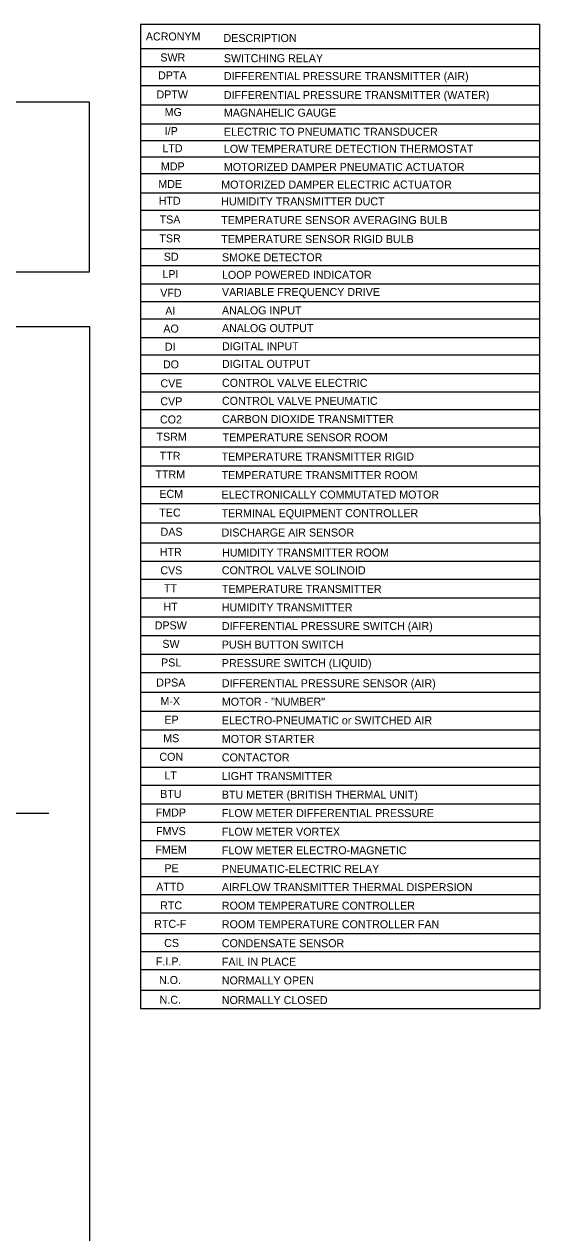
# Model space of a CAD drawing. Extents: x 10015 to 10283, y 10002 to 10184.
# Drawn here: x 10212.9 to 10255.9, y 10083.5 to 10184.2 of the extents above; entities that cross this region are included whole.
import ezdxf

# ---------------------------------------------------------------- set-up
doc = ezdxf.new("R2010")
doc.units = 0
for name, color, linetype in [('G-ANNO-TEXT', 7, 'Continuous'), ('G-DETL-LINE', 7, 'Continuous'), ('G-SCHD-LINE', 7, 'Continuous'), ('G-SCHD-TEXT', 7, 'Continuous'), ('M-ANNO-NPLT', 7, 'Continuous')]:
    doc.layers.add(name, color=color, linetype=linetype)

msp = doc.modelspace()

# ---------------------------------------------------------------- linework, layer by layer
at = {"layer": 'G-ANNO-TEXT'}
msp.add_line((10206.45, 10118.48), (10214.98, 10118.48), dxfattribs=at)
at = {"layer": 'G-DETL-LINE'}
msp.add_lwpolyline([(10127.5, 10177.76), (10218.36, 10177.76), (10218.36, 10163.56), (10127.5, 10163.56)], close=True, dxfattribs=at)
msp.add_lwpolyline([(10164.66, 10159.01), (10164.66, 10134.54), (10132.98, 10134.54), (10132.98, 10061.02), (10218.41, 10061.02), (10218.41, 10159.01), (10164.66, 10159.01)], dxfattribs=at)
at = {"layer": 'G-SCHD-LINE'}
for p, q in [((10222.64, 10184.22), (10222.65, 10102.19)), ((10222.64, 10184.22), (10255.92, 10184.22)), ((10255.92, 10184.22), (10255.94, 10102.19)), ((10222.64, 10182.19), (10255.92, 10182.19)), ((10222.64, 10180.69), (10255.92, 10180.69)), ((10222.64, 10179.1), (10255.92, 10179.1)), ((10222.64, 10177.5), (10255.92, 10177.5)), ((10222.64, 10175.91), (10255.92, 10175.91)), ((10222.64, 10174.53), (10255.92, 10174.53)), ((10222.64, 10173.16), (10255.92, 10173.16)), ((10222.64, 10171.78), (10255.92, 10171.78)), ((10222.64, 10170.16), (10255.92, 10170.16)), ((10222.64, 10168.72), (10255.92, 10168.72)), ((10222.64, 10167.07), (10255.92, 10167.07)), ((10222.64, 10165.53), (10255.92, 10165.53)), ((10222.64, 10164.1), (10255.92, 10164.1)), ((10222.64, 10162.59), (10255.92, 10162.59)), ((10222.64, 10161.12), (10255.92, 10161.12)), ((10222.64, 10159.66), (10255.92, 10159.66)), ((10222.64, 10158.11), (10255.92, 10158.11)), ((10222.64, 10156.67), (10255.92, 10156.67)), ((10222.64, 10155.12), (10255.92, 10155.12)), ((10222.64, 10153.58), (10255.92, 10153.58)), ((10222.64, 10152.1), (10255.92, 10152.1)), ((10222.64, 10150.59), (10255.92, 10150.59)), ((10222.64, 10148.99), (10255.92, 10148.99)), ((10222.64, 10147.42), (10255.92, 10147.42)), ((10222.64, 10145.71), (10255.92, 10145.71)), ((10222.64, 10144.27), (10255.92, 10144.27)), ((10222.64, 10142.68), (10255.92, 10142.68)), ((10222.64, 10141), (10255.92, 10141)), ((10222.64, 10139.47), (10255.92, 10139.47)), ((10222.64, 10137.98), (10255.92, 10137.98)), ((10222.64, 10136.41), (10255.92, 10136.41)), ((10222.64, 10134.84), (10255.92, 10134.84)), ((10222.64, 10133.27), (10255.92, 10133.27)), ((10222.64, 10131.72), (10255.92, 10131.72)), ((10222.64, 10130.21), (10255.92, 10130.21)), ((10222.64, 10128.55), (10255.92, 10128.55)), ((10222.64, 10126.99), (10255.92, 10126.99)), ((10222.64, 10125.42), (10255.92, 10125.42)), ((10222.64, 10123.89), (10255.92, 10123.89)), ((10222.64, 10122.32), (10255.92, 10122.32)), ((10222.64, 10120.8), (10255.92, 10120.8)), ((10222.64, 10119.25), (10255.92, 10119.25)), ((10222.64, 10117.72), (10255.92, 10117.72)), ((10222.64, 10116.21), (10255.92, 10116.21)), ((10222.64, 10114.7), (10255.92, 10114.7)), ((10222.64, 10113.2), (10255.92, 10113.2)), ((10222.64, 10111.69), (10255.92, 10111.69)), ((10222.64, 10110.18), (10255.92, 10110.18)), ((10222.64, 10108.46), (10255.92, 10108.46)), ((10222.64, 10106.95), (10255.92, 10106.95)), ((10222.64, 10105.44), (10255.92, 10105.44)), ((10222.64, 10103.72), (10255.92, 10103.72)), ((10222.65, 10102.19), (10255.94, 10102.19))]:
    msp.add_line(p, q, dxfattribs=at)

# ---------------------------------------------------------------- texts
at = {"layer": 'G-SCHD-TEXT'}
for s, height, p in [('ACRONYM', 0.667, (10223.08, 10182.86)), ('DESCRIPTION', 0.6667, (10229.56, 10182.73)), ('SWR', 0.667, (10224.29, 10181.11)), ('SWITCHING RELAY', 0.6667, (10229.59, 10181.05)), ('DPTA', 0.667, (10224.1, 10179.62)), ('DIFFERENTIAL PRESSURE TRANSMITTER (AIR)', 0.6667, (10229.59, 10179.56)), ('DPTW', 0.667, (10223.97, 10178.03)), ('DIFFERENTIAL PRESSURE TRANSMITTER (WATER)', 0.6667, (10229.59, 10177.98)), ('MG', 0.667, (10224.65, 10176.56)), ('MAGNAHELIC GAUGE', 0.6667, (10229.59, 10176.51)), ('I/P', 0.667, (10224.66, 10174.98)), ('ELECTRIC TO PNEUMATIC TRANSDUCER', 0.6667, (10229.59, 10174.92)), ('LTD', 0.667, (10224.46, 10173.55)), ('LOW TEMPERATURE DETECTION THERMOSTAT', 0.6667, (10229.59, 10173.5)), ('MDP', 0.667, (10224.34, 10172.04)), ('MOTORIZED DAMPER PNEUMATIC ACTUATOR', 0.6667, (10229.59, 10171.99)), ('MDE', 0.667, (10224.12, 10170.57)), ('MOTORIZED DAMPER ELECTRIC ACTUATOR', 0.6667, (10229.37, 10170.52)), ('HTD', 0.667, (10224.15, 10169.17)), ('HUMIDITY TRANSMITTER DUCT', 0.6667, (10229.37, 10169.12)), ('TSA', 0.667, (10224.23, 10167.61)), ('TEMPERATURE SENSOR AVERAGING BULB', 0.6667, (10229.37, 10167.56)), ('TSR', 0.667, (10224.21, 10166.04)), ('TEMPERATURE SENSOR RIGID BULB', 0.6667, (10229.37, 10165.98)), ('SD', 0.667, (10224.58, 10164.51)), ('SMOKE DETECTOR', 0.6667, (10229.43, 10164.46)), ('LPI', 0.667, (10224.46, 10163.06)), ('LOOP POWERED INDICATOR', 0.6667, (10229.43, 10163)), ('VFD', 0.667, (10224.28, 10161.5)), ('VARIABLE FREQUENCY DRIVE', 0.6667, (10229.43, 10161.57)), ('AI', 0.667, (10224.7, 10160)), ('ANALOG INPUT', 0.6667, (10229.43, 10160.04)), ('ANALOG OUTPUT', 0.6667, (10229.43, 10158.56)), ('AO', 0.667, (10224.54, 10158.52)), ('DI', 0.667, (10224.67, 10157.01)), ('DIGITAL INPUT', 0.6667, (10229.43, 10157.05)), ('DO', 0.667, (10224.51, 10155.54)), ('DIGITAL OUTPUT', 0.6667, (10229.43, 10155.58)), ('CVE', 0.667, (10224.3, 10153.96)), ('CONTROL VALVE ELECTRIC', 0.6667, (10229.43, 10154)), ('CVP', 0.667, (10224.29, 10152.46)), ('CONTROL VALVE PNEUMATIC', 0.6667, (10229.43, 10152.5)), ('CO2', 0.667, (10224.26, 10150.95)), ('CARBON DIOXIDE TRANSMITTER', 0.6667, (10229.43, 10150.99)), ('TSRM', 0.667, (10223.97, 10149.51)), ('TEMPERATURE SENSOR ROOM', 0.6667, (10229.48, 10149.46)), ('TTR', 0.667, (10224.24, 10147.92)), ('TEMPERATURE TRANSMITTER RIGID', 0.6667, (10229.4, 10147.86)), ('TTRM', 0.667, (10223.88, 10146.37)), ('TEMPERATURE TRANSMITTER ROOM', 0.6667, (10229.4, 10146.31)), ('ECM', 0.667, (10224.21, 10144.75)), ('ELECTRONICALLY COMMUTATED MOTOR', 0.6667, (10229.4, 10144.69)), ('HTR', 0.667, (10224.24, 10139.91)), ('HUMIDITY TRANSMITTER ROOM', 0.6667, (10229.44, 10139.86)), ('CVS', 0.667, (10224.29, 10138.38)), ('CONTROL VALVE SOLINOID', 0.6667, (10229.42, 10138.38)), ('TT', 0.667, (10224.59, 10136.89)), ('TEMPERATURE TRANSMITTER', 0.6667, (10229.42, 10136.83)), ('HT', 0.667, (10224.55, 10135.34)), ('HUMIDITY TRANSMITTER', 0.6667, (10229.42, 10135.29)), ('DPSW', 0.667, (10223.82, 10133.79)), ('DIFFERENTIAL PRESSURE SWITCH (AIR)', 0.6667, (10229.42, 10133.74)), ('SW', 0.667, (10224.46, 10132.25)), ('PUSH BUTTON SWITCH', 0.6667, (10229.42, 10132.19)), ('PSL', 0.667, (10224.35, 10130.7)), ('PRESSURE SWITCH (LIQUID)', 0.6667, (10229.42, 10130.65)), ('DPSA', 0.667, (10223.95, 10129.03)), ('DIFFERENTIAL PRESSURE SENSOR (AIR)', 0.6667, (10229.42, 10128.97)), ('M-X', 0.667, (10224.3, 10127.48)), ('MOTOR - "NUMBER"', 0.6667, (10229.42, 10127.43)), ('EP', 0.667, (10224.63, 10125.93)), ('ELECTRO-PNEUMATIC or SWITCHED AIR', 0.6667, (10229.42, 10125.88)), ('MS', 0.667, (10224.53, 10124.39)), ('MOTOR STARTER', 0.6667, (10229.42, 10124.33)), ('CON', 0.667, (10224.21, 10122.84)), ('CONTACTOR', 0.667, (10229.42, 10122.79)), ('LT', 0.667, (10224.63, 10121.29)), ('LIGHT TRANSMITTER', 0.6667, (10229.42, 10121.24)), ('BTU', 0.667, (10224.28, 10119.75)), ('BTU METER (BRITISH THERMAL UNIT)', 0.6667, (10229.42, 10119.69)), ('FMDP', 0.667, (10223.9, 10118.2)), ('FLOW METER DIFFERENTIAL PRESSURE', 0.6667, (10229.42, 10118.15)), ('FMVS', 0.667, (10223.93, 10116.65)), ('FLOW METER VORTEX', 0.6667, (10229.42, 10116.6)), ('FMEM', 0.667, (10223.87, 10115.11)), ('FLOW METER ELECTRO-MAGNETIC', 0.6667, (10229.42, 10115.05)), ('PE', 0.667, (10224.63, 10113.56)), ('PNEUMATIC-ELECTRIC RELAY', 0.6667, (10229.42, 10113.5)), ('ATTD', 0.667, (10223.94, 10112.01)), ('AIRFLOW TRANSMITTER THERMAL DISPERSION', 0.6667, (10229.42, 10111.98)), ('RTC', 0.667, (10224.27, 10110.46)), ('ROOM TEMPERATURE CONTROLLER', 0.6667, (10229.42, 10110.44)), ('RTC-F', 0.667, (10223.78, 10108.92)), ('ROOM TEMPERATURE CONTROLLER FAN', 0.6667, (10229.42, 10108.89)), ('CS', 0.667, (10224.61, 10107.33)), ('CONDENSATE SENSOR', 0.6667, (10229.42, 10107.31)), ('F.I.P.', 0.667, (10223.92, 10105.79)), ('FAIL IN PLACE', 0.6667, (10229.42, 10105.76)), ('N.O.', 0.667, (10224.18, 10104.24)), ('NORMALLY OPEN', 0.6667, (10229.42, 10104.21)), ('N.C.', 0.667, (10224.23, 10102.6)), ('NORMALLY CLOSED', 0.6667, (10229.42, 10102.57))]:
    msp.add_text(s, height=height, dxfattribs=at).set_placement(p)
at = {"layer": 'M-ANNO-NPLT'}
for s, height, p in [('TEC', 0.667, (10224.2, 10143.19)), ('TERMINAL EQUIPMENT CONTROLLER', 0.6667, (10229.4, 10143.14)), ('DAS', 0.667, (10224.31, 10141.59)), ('DISCHARGE AIR SENSOR', 0.6667, (10229.4, 10141.53))]:
    msp.add_text(s, height=height, dxfattribs=at).set_placement(p)

doc.saveas('drawing.dxf')
